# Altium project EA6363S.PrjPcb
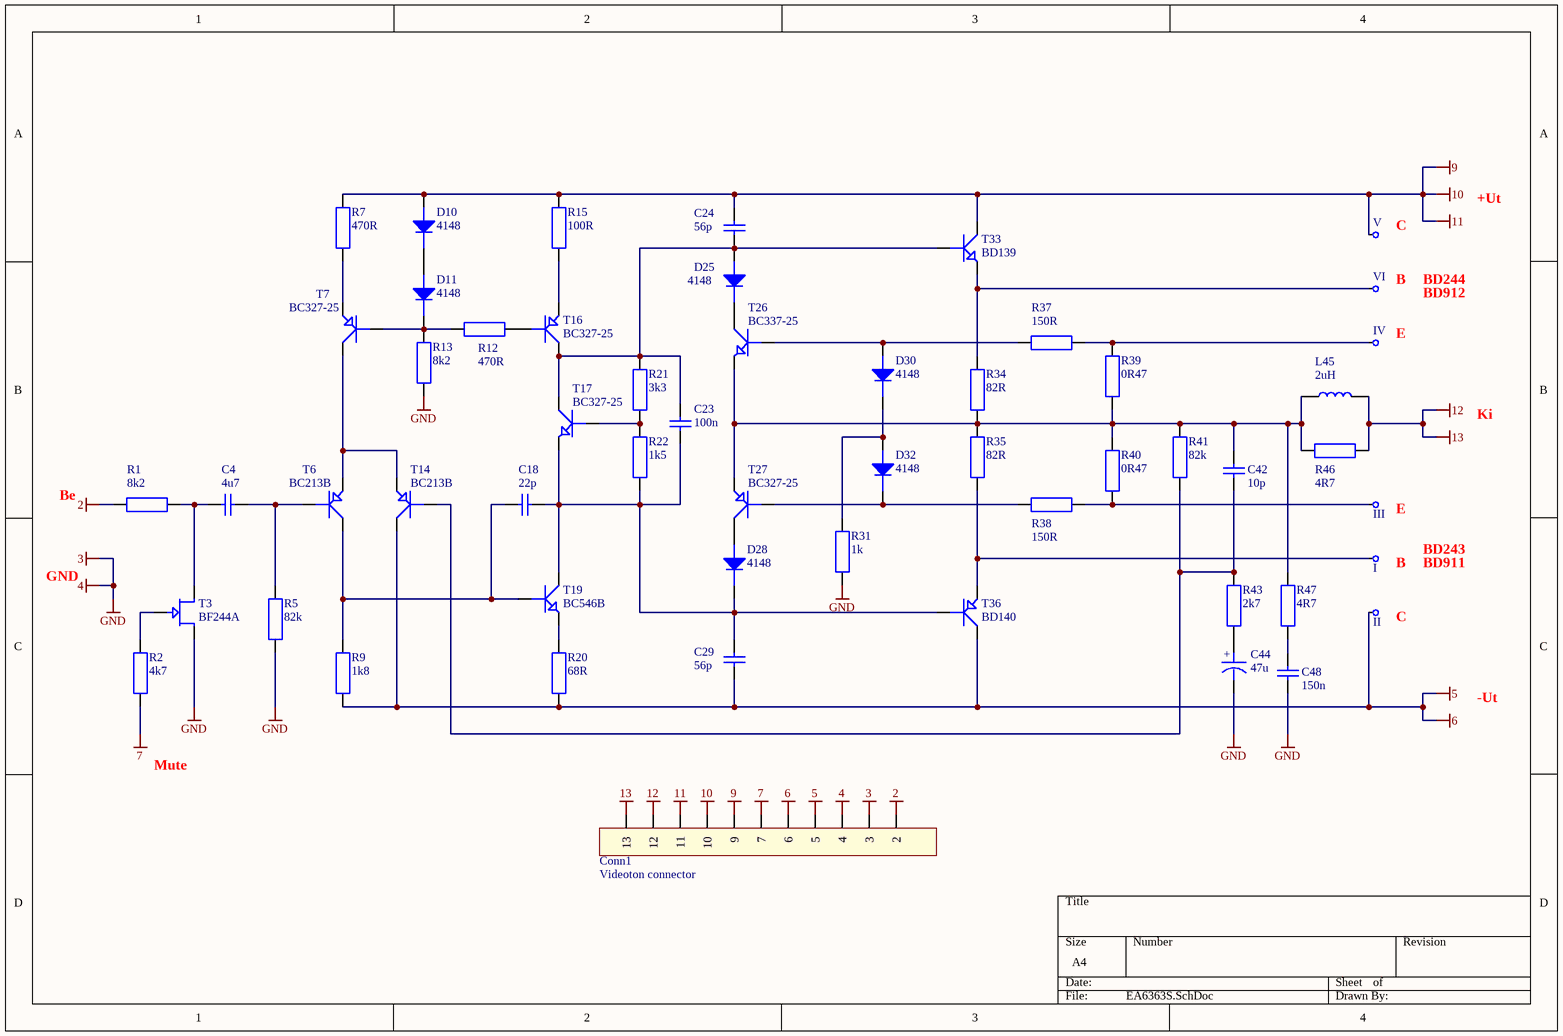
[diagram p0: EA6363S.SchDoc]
1 sheet, 55 parts. Net scope: global (net labels, ports and power ports of the same name join across sheets).
Board file: EA6363S_v2.PcbDoc

## Sheet EA6363S.SchDoc
size A4

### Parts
C4  4u7  [C2334 100V]
C18  22p  [C2441]
C23  100n  [C2332 400V]
C24  56p  [C2441]
C29  56p  [C2441]
C42  10p  [C2441]
C44  47u  [021 ASM Wishay]
C48  150n  [C2333 250V]
Conn1  Videoton connector  [Videoton connector]
D10  4148  [DO-35 3R]
D11  4148  [DO-35 3R]
D25  4148  [DO-35 3R]
D28  4148  [DO-35 3R]
D30  4148  [DO-35 3R]
D32  4148  [DO-35 3R]
I  1pin  [1pin 1.4x3]  (value not drawn)
II  1pin  [1pin 1.4x3]  (value not drawn)
III  1pin  [1pin 1.4x3]  (value not drawn)
IV  1pin  [1pin 1.4x3]  (value not drawn)
L45  2uH  [2.2 uH]
R1  8k2  [MF0207]
R2  4k7  [MF0207]
R5  82k  [MF0207]
R7  470R  [MF0207]
R9  1k8  [MF0207]
R12  470R  [MF0207]
R13  8k2  [MF0207]
R15  100R  [MF0207]
R20  68R  [MF0207]
R21  3k3  [MF0207]
R22  1k5  [MF0207]
R31  1k  [MF0207]
R34  82R  [MF0207]
R35  82R  [MF0207]
R37  150R  [MF0207]
R38  150R  [MF0207]
R39  0R47  [KNP5WS]
R40  0R47  [KNP5WS]
R41  82k  [MF0207]
R43  2k7  [MF0207]
R46  4R7  [MOR03]
R47  4R7  [MOR03]
T3  BF244A  [TO-92]
T6  BC213B  [BC557]
T7  BC327-25  [BC557]
T14  BC213B  [BC557]
T16  BC327-25  [BC557]
T17  BC327-25  [BC547]
T19  BC546B  [BC547]
T26  BC337-25  [BC547]
T27  BC327-25  [BC557]
T33  BD139  [BD139]
T36  BD140  [BD139]
V  1pin  [1pin 1.4x3]  (value not drawn)
VI  1pin  [1pin 1.4x3]  (value not drawn)

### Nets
2: Conn1.2 R1.2
3: C44.2 C48.1 Conn1.3 Conn1.4 R5.2 R13.2 R31.1 T3.S(Source)  [also labelled 4, GND]
5: C29.1 Conn1.5 Conn1.6 II.1 R9.2 R20.2 T14.C T36.C  [also labelled 6]
7: Conn1.7 R2.2
10: C24.2 Conn1.9 Conn1.10 Conn1.11 D10.A R7.1 R15.1 T33.C V.1  [also labelled 11, 9]
12: Conn1.12 Conn1.13 L45.1 R46.1  [also labelled 13]
NetC4_1: C4.1 R1.1 T3.D(Drain)
NetC4_2: C4.2 R5.1 T6.B
NetC18_1: C18.1 R9.1 T6.C T19.B
NetC18_2: C18.2 C23.1 C29.2 D28.K R22.2 T17.E T19.C T36.B
NetC23_2: C23.2 C24.1 D25.A R21.1 T16.C T17.C T33.B
NetC42_1: C42.1 R41.1 R43.2 T14.B
NetC42_2: C42.2 L45.2 R34.2 R35.1 R39.1 R40.2 R41.2 R46.2 R47.2 T26.E T27.E
NetC44_1: C44.1 R43.1
NetC48_2: C48.2 R47.1
NetD10_K: D10.K D11.A
NetD11_K: D11.K R12.1 R13.1 T7.B
NetD25_K: D25.K T26.C
NetD28_A: D28.A T27.C
NetD30_A: D30.A R37.1 T26.B
NetD30_K: D30.K D32.A R31.2
NetD32_K: D32.K R38.1 T27.B
NetI_1: I.1 R35.2 T36.E
NetIII_1: III.1 R38.2 R40.1
NetIV_1: IV.1 R37.2 R39.2
NetR2_1: R2.1 T3.G(Gate)
NetR7_2: R7.2 T7.E
NetR12_2: R12.2 T16.B
NetR15_2: R15.2 T16.E
NetR20_1: R20.1 T19.E
NetR21_2: R21.2 R22.1 T17.B
NetR34_1: R34.1 T33.E VI.1
NetT6_E: T6.E T7.C T14.E

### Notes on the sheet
- (near V) C
- +Ut
- (near VI) B
- BD244
- BD912
- (near IV) E
- Ki
- (near R1) Be
- (near III) E
- GND
- (near I) B
- BD243
- BD911
- (near II) C
- -Ut
- Mute

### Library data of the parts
C4 C18 C23 C24 C29 C42 C48 = CAP
C44 = CAP POL
D10 D11 D25 D28 D30 D32 = Dioda
L45 = Inductor_1
R1 R2 R5 R7 R9 R12 R13 R15 R20-R22 R31 R34 R35 R37-R41 R43 R46 R47 = RES_THT
T3 = JFET-N
T6 T7 T14 T16 T27 T36 = PNP
T17 T19 T26 T33 = NPN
